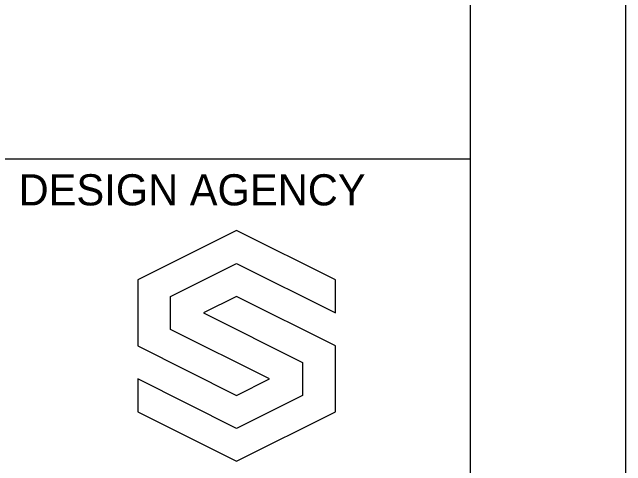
# Model space of a CAD drawing. Extents: x -50 to 112, y -27 to 22.
# Drawn here: x 71.03 to 73, y 3.514 to 4.97 of the extents above; entities that cross this region are included whole.
import ezdxf

# ---------------------------------------------------------------- set-up
doc = ezdxf.new("R2010")
doc.units = 0
for name, color, linetype in [('Default', 7, 'Continuous'), ('SH_Border', 7, 'Continuous'), ('SH_Cut_Line', 7, 'Continuous'), ('SH_Data', 7, 'Continuous')]:
    doc.layers.add(name, color=color, linetype=linetype)

msp = doc.modelspace()

# ---------------------------------------------------------------- linework, layer by layer
at = {"layer": 'Default'}
for p, q in [((71.75, 4.2693), (71.4325, 4.1106)), ((72.0675, 4.1106), (71.75, 4.2693)), ((71.5383, 4.0576), (71.75, 4.1635)), ((71.75, 4.1635), (72.0675, 4.0047)), ((71.4325, 4.1106), (71.4325, 3.8989)), ((72.0675, 4.0047), (72.0675, 4.1106)), ((71.5383, 3.9518), (71.5383, 4.0576)), ((71.75, 4.0576), (71.6442, 4.0047)), ((72.0675, 3.8989), (71.75, 4.0576)), ((71.6442, 4.0047), (71.9617, 3.8459)), ((71.8558, 3.793), (71.5383, 3.9518)), ((71.4325, 3.8989), (71.75, 3.7401)), ((72.0675, 3.6872), (72.0675, 3.8989)), ((71.9617, 3.8459), (71.9617, 3.7401)), ((71.75, 3.6342), (71.4325, 3.793)), ((71.4325, 3.793), (71.4325, 3.6872)), ((71.75, 3.7401), (71.8558, 3.793)), ((71.9617, 3.7401), (71.75, 3.6342)), ((71.4325, 3.6872), (71.75, 3.5284)), ((71.75, 3.5284), (72.0675, 3.6872))]:
    msp.add_line(p, q, dxfattribs=at)
for points in [[(71.75, 4.2693), (71.4325, 4.1106), (71.4325, 3.8989), (71.75, 3.7401), (71.8558, 3.793), (71.5383, 3.9518), (71.5383, 4.0576), (71.75, 4.1635), (72.0675, 4.0047), (72.0675, 4.1106), (71.75, 4.2693)], [(71.75, 3.5284), (72.0675, 3.6872), (72.0675, 3.8989), (71.75, 4.0576), (71.6442, 4.0047), (71.9617, 3.8459), (71.9617, 3.7401), (71.75, 3.6342), (71.4325, 3.793), (71.4325, 3.6872), (71.75, 3.5284)]]:
    msp.add_lwpolyline(points, dxfattribs=at)
at = {"layer": 'SH_Border'}
msp.add_line((71, 4.5), (72.5, 4.5), dxfattribs=at)
msp.add_lwpolyline([(40.5, 21.5), (72.5, 21.5), (72.5, 0.5), (40.5, 0.5)], close=True, dxfattribs=at)
at = {"layer": 'SH_Cut_Line'}
msp.add_lwpolyline([(39, 0), (73, 0), (73, 22), (39, 22)], close=True, dxfattribs=at)

# ---------------------------------------------------------------- texts
at = {"layer": 'SH_Data'}
msp.add_text('DESIGN AGENCY', height=0.1, dxfattribs=at).set_placement((71.05, 4.35))

doc.saveas('drawing.dxf')
